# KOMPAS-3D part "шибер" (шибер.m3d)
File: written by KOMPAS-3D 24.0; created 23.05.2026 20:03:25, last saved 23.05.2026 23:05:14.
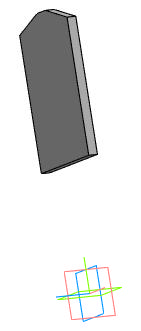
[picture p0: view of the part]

Document properties: Автор: R2D2; Полное имя файла: E:\Работа\Зайцев\GVKR1331E-1W-Fb-2P Задвижка шиберная DN.ru Ду50-300 Ру16-10-6\исходные материалы\DN125\шибер.m3d

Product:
- Part/product: шибер
    Масса: 1.385554
    Раздел спецификации: Прочие изделия
    Примечание: D040-08800

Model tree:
1. Эскиз:5  (with: Грань.Элемент выдавливания:1, Вершина.Элемент выдавливания:15)
2. Элемент выдавливания:6
     Расстояние 1 = 10

Referenced files in E:\Работа\Зайцев\GVKR1331E-1W-Fb-2P Задвижка шиберная DN.ru Ду50-300 Ру16-10-6\исходные материалы\DN125\: GVKR1331E-1W-Fb-2P Задвижка шиберная с выдвижным штоком DN.ru Ду125 Ру10.a3d
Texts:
  Затвор дисковый DN.ru Ду Ру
